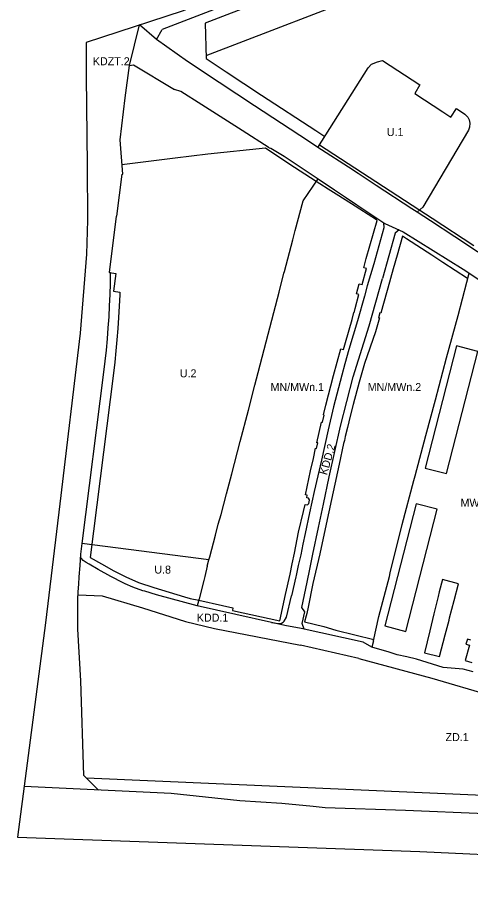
# Model space of a CAD drawing. Extents: x 7427060 to 7429122, y 5545301 to 5546237.
# Drawn here: x 7427164 to 7427447, y 5545402 to 5545952 of the extents above; entities that cross this region are included whole.
import ezdxf

# ---------------------------------------------------------------- set-up
doc = ezdxf.new("R2010")
doc.units = 0
for name, color, linetype in [('LIN_linia regulacyjna_1', 7, 'Continuous'), ('LIN_Linia Zabudowy Nieprzekraczalna', 7, 'Continuous'), ('LIN_Linia Zabudowy Obowiązujaca', 7, 'Continuous'), ('LIN_Linie Rozgraniczajace', 7, 'Continuous'), ('TXT_Oznaczenia Przeznaczenia', 7, 'Continuous')]:
    doc.layers.add(name, color=color, linetype=linetype)

msp = doc.modelspace()

# ---------------------------------------------------------------- linework, layer by layer
at = {"layer": 'LIN_linia regulacyjna_1'}
msp.add_lwpolyline([(7427281.46, 5545927.91), (7427390.14, 5545969.83), (7427390.16, 5545969.84), (7427407.8, 5545976.21), (7427426.59, 5545982.95)], dxfattribs=at)
at = {"layer": 'LIN_Linia Zabudowy Nieprzekraczalna'}
for p, q in [((7427280.8, 5545948.02), (7427281.53, 5545925.95)), ((7427281.53, 5545925.95), (7427293.97, 5545917.67)), ((7427293.97, 5545917.67), (7427316.1, 5545903.2)), ((7427316.1, 5545903.2), (7427349.94, 5545881.02)), ((7427349.94, 5545881.02), (7427355.62, 5545877.26)), ((7427427.29, 5545552.58), (7427430.87, 5545566.19)), ((7427417.98, 5545554.97), (7427427.29, 5545552.58))]:
    msp.add_line(p, q, dxfattribs=at)
for points in [[(7427416.22, 5545999.42), (7427401.36, 5545994.08), (7427383.63, 5545987.68), (7427383.42, 5545987.61), (7427280.8, 5545948.02)], [(7427350.24, 5545849.24), (7427333.07, 5545860.17), (7427318.62, 5545870.03), (7427282.47, 5545866.3), (7427262.14, 5545863.82), (7427228.82, 5545859.6)], [(7427352.42, 5545872.18), (7427414.39, 5545831.76), (7427422.77, 5545826.42), (7427448.9, 5545809.21)], [(7427276.81, 5545587.71), (7427291.69, 5545584.42), (7427298.24, 5545583.04), (7427297.88, 5545581.4), (7427327.62, 5545574.85), (7427331.05, 5545591.33), (7427333.97, 5545604.05), (7427335.33, 5545610.38), (7427336.76, 5545617.04), (7427339.26, 5545630.24), (7427342.25, 5545643.18), (7427343.31, 5545647.59), (7427344.6, 5545647.36), (7427345.09, 5545647.56), (7427345.57, 5545648.17), (7427346.04, 5545650.2), (7427346.05, 5545650.52), (7427345.39, 5545651.47), (7427344.31, 5545651.73), (7427344.68, 5545653.26), (7427343.51, 5545653.51), (7427346.75, 5545668.64), (7427348.47, 5545676.24), (7427349.92, 5545682.65), (7427350.45, 5545682.53), (7427351.23, 5545685.98), (7427350.7, 5545686.1), (7427353.62, 5545698.98), (7427354.14, 5545698.84), (7427355.32, 5545703.37), (7427354.73, 5545703.52), (7427356.26, 5545709.63), (7427361.06, 5545728.03), (7427365.65, 5545744.8), (7427367.4, 5545744.31), (7427368.63, 5545748.7), (7427372.65, 5545763.13), (7427373.82, 5545767.32), (7427373.97, 5545767.28), (7427374.71, 5545769.93), (7427374.56, 5545769.97), (7427377.01, 5545778.73), (7427375.39, 5545779.18), (7427377.15, 5545785.41), (7427378.99, 5545784.9), (7427381.73, 5545794.8), (7427379.95, 5545795.29), (7427381.58, 5545801.06), (7427388.31, 5545824.81), (7427387.95, 5545825.36), (7427372.3, 5545835.21), (7427362.8, 5545841.22), (7427357.81, 5545844.41), (7427352.6, 5545847.74), (7427350.24, 5545849.24)], [(7427404.17, 5545815.04), (7427400.88, 5545803.27), (7427398.48, 5545794.71), (7427395.12, 5545782.57), (7427391.98, 5545771.63), (7427390.7, 5545767.08)], [(7427422.57, 5545803.13), (7427406.73, 5545813.42), (7427404.17, 5545815.04)], [(7427444.92, 5545788.59), (7427429.51, 5545798.69), (7427422.57, 5545803.13)], [(7427221.04, 5545792.37), (7427224.97, 5545791.75), (7427223.46, 5545780.7), (7427227.44, 5545780.17), (7427227.39, 5545778.4), (7427227.11, 5545771.39), (7427226.74, 5545764.38), (7427226.27, 5545757.38), (7427225.71, 5545750.39), (7427225.06, 5545743.4), (7427224.31, 5545736.42), (7427223.48, 5545729.48), (7427208.88, 5545614.45), (7427215.97, 5545610.37), (7427223.65, 5545606.17), (7427231.22, 5545602.27), (7427239.16, 5545598.78), (7427248.82, 5545595.79), (7427267.92, 5545589.9), (7427271.51, 5545588.88), (7427276.81, 5545587.71)], [(7427389.83, 5545763.99), (7427388.6, 5545759.63), (7427387.35, 5545755.32), (7427380.44, 5545735.59), (7427377.15, 5545723.86), (7427373.45, 5545709.93), (7427371.51, 5545702.67), (7427369.79, 5545695.55), (7427368.46, 5545689.98), (7427367.85, 5545687.47), (7427367.4, 5545685.57), (7427364.53, 5545672.72), (7427357.13, 5545638.09)], [(7427390.7, 5545767.08), (7427390.06, 5545767.24), (7427389.31, 5545764.12), (7427389.83, 5545763.99)], [(7427357.13, 5545638.08), (7427352.55, 5545616.75), (7427348.22, 5545598.23), (7427345.25, 5545583.5), (7427344.38, 5545579.52), (7427344.06, 5545578.04), (7427343, 5545574.16), (7427355.04, 5545571.3), (7427362.45, 5545569.14), (7427386.19, 5545563.21)], [(7427430.87, 5545566.19), (7427433.29, 5545575.39), (7427433.67, 5545576.83), (7427436.49, 5545587.47), (7427439.31, 5545598.06), (7427429.2, 5545600.64), (7427427.16, 5545592.97), (7427426.46, 5545590.04), (7427423.87, 5545579.34), (7427421.29, 5545568.65), (7427417.98, 5545554.97)]]:
    msp.add_lwpolyline(points, dxfattribs=at)
at = {"layer": 'LIN_Linia Zabudowy Obowiązujaca'}
for points in [[(7427418.42, 5545670.22), (7427431.7, 5545666.82), (7427451.28, 5545743.12), (7427438.02, 5545746.53)], [(7427406.38, 5545568.24), (7427425.97, 5545644.55), (7427412.76, 5545647.99), (7427393.09, 5545571.7)]]:
    msp.add_lwpolyline(points, close=True, dxfattribs=at)
msp.add_lwpolyline([(7427446.87, 5545562.79), (7427444.76, 5545563.37), (7427443.91, 5545560.23), (7427446.01, 5545559.65), (7427443.37, 5545550), (7427447.6, 5545548.85)], dxfattribs=at)
at = {"layer": 'LIN_Linie Rozgraniczajace'}
for p, q in [((7427233.52, 5545921.66), (7427239.78, 5545946.98)), ((7427250.42, 5545937.82), (7427239.78, 5545946.98)), ((7427250.42, 5545937.82), (7427254.05, 5545944.13)), ((7427233.52, 5545921.66), (7427236.02, 5545922.14)), ((7427236.02, 5545922.14), (7427261.74, 5545906.71)), ((7427265.53, 5545905.4), (7427261.74, 5545906.71)), ((7427342.14, 5545837.11), (7427351.41, 5545850.99)), ((7427337.15, 5545818.54), (7427342.14, 5545837.11)), ((7427335.6, 5545812.77), (7427337.15, 5545818.54)), ((7427330.43, 5545793.08), (7427335.6, 5545812.77)), ((7427327.01, 5545780.08), (7427330.12, 5545791.92)), ((7427330.12, 5545791.92), (7427330.43, 5545793.08)), ((7427444.34, 5545786.34), (7427445.83, 5545792.08)), ((7427438.96, 5545765.62), (7427444.34, 5545786.34)), ((7427326.07, 5545776.12), (7427327.01, 5545780.08)), ((7427318.98, 5545749.02), (7427326.07, 5545776.12)), ((7427431.66, 5545739.04), (7427438.96, 5545765.62)), ((7427313.99, 5545730.01), (7427318.98, 5545749.02)), ((7427302.73, 5545686.85), (7427307.91, 5545706.38)), ((7427297.47, 5545666.71), (7427302.73, 5545686.85)), ((7427294.2, 5545654.27), (7427297.47, 5545666.71)), ((7427411.38, 5545662.56), (7427412.18, 5545665.48)), ((7427290.92, 5545641.21), (7427294.2, 5545654.27)), ((7427289.03, 5545635.23), (7427290.92, 5545641.21)), ((7427283.04, 5545612.87), (7427203.79, 5545623.23)), ((7427389.51, 5545577.54), (7427396.03, 5545602.61)), ((7427386.02, 5545562.46), (7427389.51, 5545577.54)), ((7427203.17, 5545537.32), (7427201.33, 5545569.59)), ((7427377, 5545551.27), (7427340.35, 5545559.67)), ((7427386.02, 5545562.46), (7427385.08, 5545558.41)), ((7427377, 5545551.27), (7427422.46, 5545538.97)), ((7427205.06, 5545478.22), (7427203.17, 5545537.32)), ((7427422.46, 5545538.97), (7427522.78, 5545509.77)), ((7427205.06, 5545478.22), (7427214.07, 5545469.22)), ((7427585.14, 5545459.97), (7427206.59, 5545476.7))]:
    msp.add_line(p, q, dxfattribs=at)
for points in [[(7427788.48, 5545964.44), (7427727.81, 5545988.89), (7427677.19, 5546010.17), (7427625.84, 5546029.97), (7427604.02, 5546035.69), (7427575.52, 5546041.68), (7427542.04, 5546043.19), (7427510.38, 5546042.02), (7427490.71, 5546040.43), (7427471.03, 5546035.51), (7427448.97, 5546027.41), (7427402.2, 5546009.67), (7427266.44, 5545955.68), (7427206.38, 5545936.07)], [(7427483.69, 5546030.36), (7427474.59, 5546027), (7427449.83, 5546018.09), (7427431.86, 5546011.64), (7427427.27, 5546009.82), (7427416.8, 5546006), (7427399.33, 5545999.73), (7427381.57, 5545993.32), (7427381.3, 5545993.22), (7427254.05, 5545944.13)], [(7427206.38, 5545936.07), (7427206.36, 5545914.88), (7427207.15, 5545859.14), (7427207.2, 5545825.05), (7427206.65, 5545803.79), (7427202.76, 5545754.61), (7427190.08, 5545647.92), (7427181.06, 5545573.67), (7427163.56, 5545439.73), (7427415.14, 5545430.84), (7427629.43, 5545420.86), (7427780.19, 5545413.81), (7427861.1, 5545402.15)], [(7427503.73, 5545770.87), (7427476.98, 5545788.24), (7427457.14, 5545801.37), (7427451.1, 5545805.36), (7427436.95, 5545814.7), (7427421.68, 5545824.74), (7427413.31, 5545830.08), (7427410.1, 5545832.16), (7427387.82, 5545846.64), (7427376.42, 5545854.14), (7427370.41, 5545858.09), (7427353.59, 5545869.02), (7427351.35, 5545870.49), (7427345.54, 5545874.34), (7427311.72, 5545896.51), (7427289.56, 5545910.99), (7427269.82, 5545924.14), (7427250.42, 5545937.82)], [(7427221.68, 5545792.27), (7427221.04, 5545792.37), (7427225.47, 5545827.67), (7427225.62, 5545827.64), (7427228.92, 5545853.81), (7427229.27, 5545853.77), (7427227.6, 5545875.29), (7427230.89, 5545901.58), (7427233.52, 5545921.66)], [(7427351.35, 5545870.49), (7427382.66, 5545920.17), (7427384.93, 5545922.43), (7427388.58, 5545924.01), (7427391.61, 5545924.81), (7427415.1, 5545909.68), (7427411.86, 5545904.09), (7427429.46, 5545892.75), (7427434.46, 5545889.49), (7427437.9, 5545894.84), (7427443.24, 5545891.35), (7427444.99, 5545889.49), (7427445.91, 5545887.67), (7427446.36, 5545885.69), (7427446.15, 5545883.16), (7427445.43, 5545881.24), (7427416.86, 5545833.29), (7427413.31, 5545830.08)], [(7427320.83, 5545870.25), (7427303.89, 5545881.01), (7427278.67, 5545897.08), (7427265.53, 5545905.4)], [(7427320.83, 5545870.25), (7427321.97, 5545870.14), (7427330.19, 5545865.13), (7427351.41, 5545850.99), (7427361.74, 5545844.05), (7427368.67, 5545839.41), (7427375.73, 5545834.66), (7427393.21, 5545822.9), (7427404.58, 5545817.89), (7427442.15, 5545794.5), (7427471.16, 5545775.4)], [(7427392.34, 5545823.49), (7427392.47, 5545820.25), (7427386.2, 5545797.83)], [(7427402.07, 5545818.99), (7427399.67, 5545816.87), (7427391.63, 5545788.63)], [(7427386.2, 5545797.83), (7427382.22, 5545784.01), (7427380.39, 5545777.6), (7427376, 5545762.19), (7427370.66, 5545744.27), (7427368.11, 5545735.31), (7427366.24, 5545728.32), (7427361.08, 5545708.43), (7427357.66, 5545694.07), (7427353.49, 5545675.11), (7427348.98, 5545655.59), (7427345.99, 5545642.38), (7427343.27, 5545629.33), (7427341.91, 5545622.72), (7427340.58, 5545616.19), (7427338.92, 5545609.52), (7427337.67, 5545603.19), (7427337.49, 5545602.37), (7427334.79, 5545590.47)], [(7427217.53, 5545730.23), (7427218.35, 5545737.1), (7427219.09, 5545744), (7427219.73, 5545750.9), (7427220.28, 5545757.82), (7427220.75, 5545764.74), (7427221.12, 5545771.67), (7427221.4, 5545778.6), (7427221.58, 5545785.54), (7427221.68, 5545792.27)], [(7427343.1, 5545580.51), (7427341.32, 5545583.23), (7427344.52, 5545599), (7427346.25, 5545607.14), (7427348.23, 5545616.5), (7427351.72, 5545633.07), (7427354.74, 5545647.67), (7427358.38, 5545664.71), (7427365.46, 5545696.47), (7427369.42, 5545711.83), (7427373.42, 5545727.16), (7427383.3, 5545759.09), (7427391.63, 5545788.63)], [(7427412.18, 5545665.48), (7427418.9, 5545690.58), (7427424.8, 5545712.8), (7427431.66, 5545739.04)], [(7427203.09, 5545616.48), (7427203.95, 5545623.21), (7427217.53, 5545730.23)], [(7427307.91, 5545706.38), (7427311.98, 5545721.94), (7427313.99, 5545730.01)], [(7427396.03, 5545602.61), (7427396.57, 5545604.76), (7427404.09, 5545635), (7427411.38, 5545662.56)], [(7427282.16, 5545609.05), (7427283.04, 5545612.87), (7427283.86, 5545614.83), (7427287.25, 5545628.45), (7427289.03, 5545635.23)], [(7427201.33, 5545569.59), (7427201.22, 5545574.28), (7427201.18, 5545578.98), (7427201.22, 5545583.67), (7427201.33, 5545588.36), (7427201.52, 5545593.05), (7427201.78, 5545597.73), (7427202.11, 5545602.41), (7427202.69, 5545609.52), (7427203.09, 5545616.48)], [(7427275.92, 5545584.24), (7427250.45, 5545591.13), (7427243.04, 5545593.34), (7427241.92, 5545593.67), (7427235.69, 5545595.93), (7427230.91, 5545598.04), (7427229.5, 5545598.66), (7427221.78, 5545602.64), (7427214.01, 5545606.88), (7427208.24, 5545610.2), (7427206.46, 5545611.35), (7427204.53, 5545612.59), (7427203.56, 5545613.79), (7427202.96, 5545614.25)], [(7427282.16, 5545609.05), (7427280.64, 5545602.49), (7427280, 5545600.03), (7427277.06, 5545588.66), (7427275.92, 5545584.24)], [(7427201.44, 5545591.17), (7427216.45, 5545590.51), (7427241.59, 5545582.97), (7427268.56, 5545574.41), (7427286.72, 5545570.04), (7427340.35, 5545559.67)], [(7427322.22, 5545573.9), (7427326.71, 5545573.3), (7427327.71, 5545573.26), (7427328.63, 5545573.47), (7427329.56, 5545573.96), (7427330.29, 5545574.65), (7427331.77, 5545577.08), (7427334.79, 5545590.47)], [(7427379.69, 5545561.57), (7427340.85, 5545570), (7427330.63, 5545572.01), (7427322.22, 5545573.9), (7427299.94, 5545578.89), (7427275.92, 5545584.24)], [(7427342.67, 5545569.6), (7427341.55, 5545573.26), (7427343.1, 5545580.51)], [(7427429.65, 5545545.83), (7427412.92, 5545551.02), (7427406.91, 5545552.38), (7427400.95, 5545553.62), (7427395.87, 5545555.26), (7427385.08, 5545558.41), (7427379.69, 5545561.57)], [(7427448.4, 5545543.04), (7427442.24, 5545544.7), (7427429.65, 5545545.83)], [(7427744.57, 5545442.93), (7427713.99, 5545444.18), (7427707.91, 5545444.43), (7427655.72, 5545446.06), (7427605.76, 5545448.17), (7427555.68, 5545450.21), (7427505.83, 5545452.26), (7427455.88, 5545454.34), (7427406.01, 5545456.38), (7427355.95, 5545458.17), (7427348.42, 5545458.9), (7427328.81, 5545460.79), (7427302.55, 5545462.38), (7427259.67, 5545467.06), (7427167.7, 5545471.41)]]:
    msp.add_lwpolyline(points, dxfattribs=at)

# ---------------------------------------------------------------- texts
at = {"layer": 'TXT_Oznaczenia Przeznaczenia'}
for s, rotation, p in [('KDZT.2', 360, (7427210.62, 5545921.81)), ('U.1', 360, (7427394.41, 5545877.61)), ('U.2', 360, (7427264.99, 5545726.93)), ('KDD.2', 74.0102, (7427356.95, 5545665.57)), ('MW.4', 360, (7427440.5, 5545646.07)), ('ZD.1', 360, (7427431.11, 5545499.78))]:
    msp.add_text(s, height=5, rotation=rotation, dxfattribs=at).set_placement(p)
for s, p in [('MN/MWn.1', (7427321.72, 5545718.38)), ('MN/MWn.2', (7427382.46, 5545718.38)), ('U.8', (7427249.06, 5545604.36)), ('KDD.1', (7427275.64, 5545574.36))]:
    msp.add_text(s, height=5, dxfattribs=at).set_placement(p)

doc.saveas('drawing.dxf')
